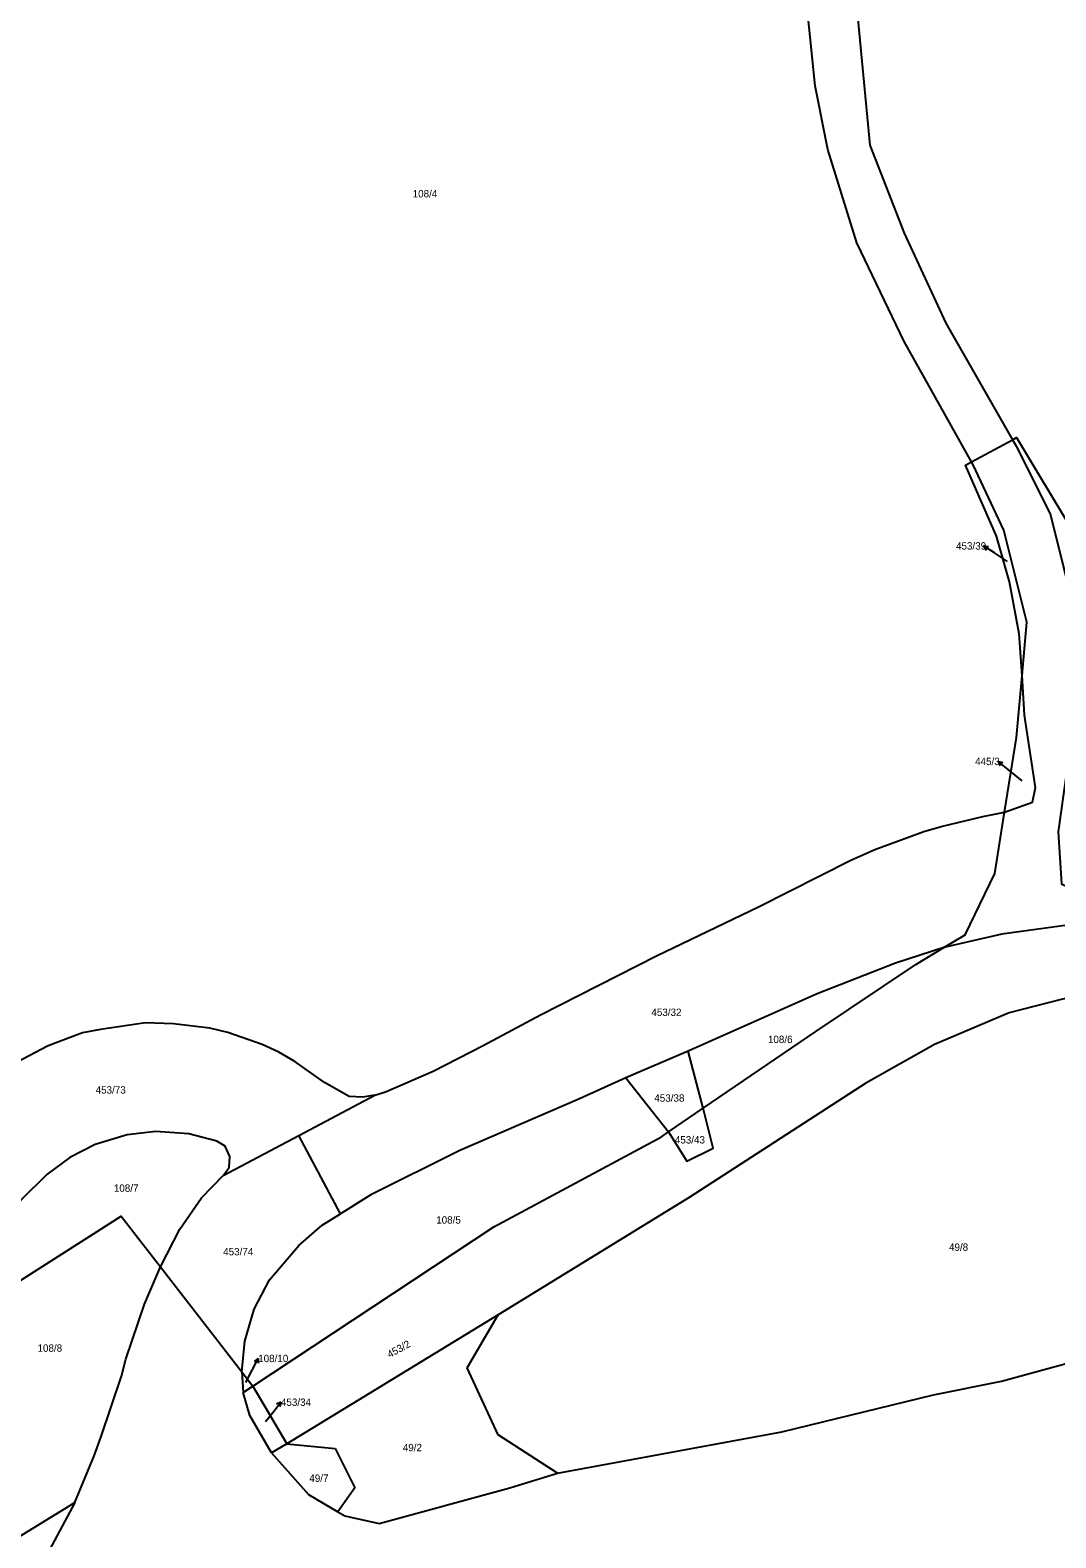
# Model space of a CAD drawing. Extents: x -882150 to -879379, y -1022570 to -1019819.
# Drawn here: x -880115.3 to -879878.6, y -1020796.9 to -1020448.8 of the extents above; entities that cross this region are included whole.
import ezdxf

# ---------------------------------------------------------------- set-up
doc = ezdxf.new("R2010")
doc.units = 0
for name, color, linetype in [('Hranice parcel', 7, 'Continuous'), ('Parcelní čísla', 7, 'Continuous'), ('Pop  PČ popisy', 7, 'Continuous')]:
    doc.layers.add(name, color=color, linetype=linetype)

msp = doc.modelspace()

# ---------------------------------------------------------------- linework, layer by layer
at = {"layer": 'Hranice parcel'}
for p, q in [((-879898.06, -1020548.48), (-879888.6, -1020543.4)), ((-879963.44, -1020684.54), (-879977.82, -1020690.75)), ((-879960.03, -1020697.74), (-879963.44, -1020684.54)), ((-879977.82, -1020690.75), (-879967.98, -1020703.17)), ((-880053.28, -1020704), (-880035.79, -1020694.72)), ((-879967.98, -1020703.17), (-879960.03, -1020697.74)), ((-880070.77, -1020713.27), (-880053.28, -1020704)), ((-880043.69, -1020722.08), (-880053.28, -1020704)), ((-880085.25, -1020734.33), (-880066.49, -1020758.57)), ((-880007.29, -1020745.44), (-880056.08, -1020775.19)), ((-880014.47, -1020757.68), (-880007.29, -1020745.44)), ((-880066.49, -1020758.57), (-880063.93, -1020761.87)), ((-880066.49, -1020758.57), (-880066.15, -1020763.39)), ((-880007.34, -1020773.15), (-880014.47, -1020757.68)), ((-880066.15, -1020763.39), (-880063.93, -1020761.87)), ((-880063.93, -1020761.87), (-880056.08, -1020775.19)), ((-880056.08, -1020775.19), (-880059.59, -1020777.26)), ((-880056.08, -1020775.19), (-880044.95, -1020776.27)), ((-879993.6, -1020781.97), (-880007.34, -1020773.15))]:
    msp.add_line(p, q, dxfattribs=at)
for points in [[(-879898.06, -1020548.48), (-879913.62, -1020520.69), (-879924.52, -1020497.9), (-879931.26, -1020476.35), (-879934.19, -1020461.7), (-879938.41, -1020420.22), (-879947.88, -1020362.58), (-879952, -1020338.2), (-879958.23, -1020317.82), (-879965.31, -1020303.46), (-879975.02, -1020294.36), (-880006.56, -1020250.49), (-880042.35, -1020206.21)], [(-880019.8, -1020217.31), (-880003.48, -1020236.2), (-879967.5, -1020277.69), (-879952.67, -1020298.78), (-879946.03, -1020310.63), (-879939.11, -1020336.56), (-879926.82, -1020417.09), (-879924.34, -1020446.28), (-879921.53, -1020475.37), (-879913.62, -1020495.71), (-879903.98, -1020516.47), (-879888.6, -1020543.4)], [(-879888.6, -1020543.4), (-879887.68, -1020542.9), (-879874.66, -1020564.64), (-879869.28, -1020574.02), (-879866.55, -1020579.31), (-879865.33, -1020582.41), (-879862.95, -1020589.58), (-879860.41, -1020600.26), (-879858.85, -1020610.83), (-879857.98, -1020621.89), (-879856.66, -1020625.28), (-879854.09, -1020626.63), (-879845.37, -1020627.31), (-879834.53, -1020628.82), (-879823.81, -1020631.02), (-879808.01, -1020635.54), (-879797.85, -1020639.13), (-879773.76, -1020649.14), (-879769.33, -1020652.27), (-879772.63, -1020658.91)], [(-879888.6, -1020543.4), (-879887.69, -1020544.98), (-879879.83, -1020560.74), (-879873.67, -1020585.51), (-879874.91, -1020611.47), (-879878.08, -1020633.92), (-879877.33, -1020645.9), (-879869.99, -1020649.38), (-879830.84, -1020645.01), (-879800.86, -1020646.94), (-879787.95, -1020649.9), (-879776.47, -1020654.35), (-879772.63, -1020658.91)], [(-879886.42, -1020597.82), (-879887.06, -1020588.22), (-879889.32, -1020576.23), (-879892.34, -1020565.69), (-879899.5, -1020549.25), (-879898.06, -1020548.48)], [(-879886.42, -1020597.82), (-879885.35, -1020585.52), (-879890.65, -1020564.27), (-879897.68, -1020549.16), (-879898.06, -1020548.48)], [(-879890.44, -1020629.39), (-879887.67, -1020612.12), (-879886.42, -1020597.82)], [(-879890.44, -1020629.39), (-879884.02, -1020627.07), (-879883.29, -1020623.66), (-879885.82, -1020606.97), (-879886.42, -1020597.82)], [(-880035.79, -1020694.72), (-880033.31, -1020693.92), (-880022.31, -1020689.21), (-880010.79, -1020683.27), (-879997.55, -1020676.15), (-879970.76, -1020662.58), (-879947.22, -1020651.2), (-879925.96, -1020640.49), (-879920.43, -1020638), (-879909.12, -1020633.87), (-879905.06, -1020632.66), (-879895.46, -1020630.4), (-879890.44, -1020629.39)], [(-879904.5, -1020660.66), (-879899.55, -1020657.68), (-879892.72, -1020643.57), (-879890.44, -1020629.39)], [(-879817.33, -1020662), (-879838.04, -1020655.79), (-879870.99, -1020656.01), (-879875.36, -1020655.41), (-879891.09, -1020657.52), (-879904.5, -1020660.66)], [(-879904.5, -1020660.66), (-879915.62, -1020664.22), (-879933.72, -1020671.33), (-879963.44, -1020684.54)], [(-879960.03, -1020697.74), (-879934.03, -1020679.99), (-879910.9, -1020664.51), (-879904.5, -1020660.66)], [(-879805.81, -1020667.04), (-879831.43, -1020664.89), (-879855.31, -1020667.58), (-879877.4, -1020672.6), (-879889.36, -1020675.71), (-879906.65, -1020682.99), (-879922.47, -1020691.94), (-879963.22, -1020718.34), (-880007.29, -1020745.44)], [(-880035.79, -1020694.72), (-880038.55, -1020695.14), (-880041.67, -1020695.04), (-880047.39, -1020691.8), (-880054.24, -1020686.91), (-880057.91, -1020684.79), (-880061.74, -1020683), (-880069.71, -1020680.22), (-880073.85, -1020679.23), (-880082.24, -1020678.22), (-880088.65, -1020678.05), (-880099.06, -1020679.52), (-880103.2, -1020680.35), (-880111.13, -1020683.34), (-880118.61, -1020687.27)], [(-879977.82, -1020690.75), (-879988.58, -1020695.59), (-880016.12, -1020707.47), (-880036.67, -1020717.69), (-880043.69, -1020722.08)], [(-879967.98, -1020703.17), (-879963.77, -1020709.98), (-879957.66, -1020706.93), (-879960.03, -1020697.74)], [(-880070.77, -1020713.27), (-880069.41, -1020711.42), (-880069.23, -1020708.91), (-880070.33, -1020706.52), (-880072.26, -1020705.33), (-880078.68, -1020703.61), (-880086.33, -1020703.09), (-880092.94, -1020703.88), (-880100.29, -1020706.14), (-880106.13, -1020709.1), (-880111.46, -1020713.02), (-880117.31, -1020718.77), (-880123.56, -1020726.71), (-880139.93, -1020751.73)], [(-880063.93, -1020761.87), (-880008.32, -1020725.12), (-879969.65, -1020704.31), (-879967.98, -1020703.17)], [(-880085.25, -1020734.33), (-880080.73, -1020725.62), (-880075.78, -1020718.44), (-880070.77, -1020713.27)], [(-880139.93, -1020751.73), (-880094.28, -1020722.66), (-880085.25, -1020734.33)], [(-880066.49, -1020758.57), (-880065.79, -1020751.53), (-880063.64, -1020744.15), (-880060.06, -1020737.33), (-880053.32, -1020729.4), (-880047.93, -1020724.74), (-880043.69, -1020722.08)], [(-880104.98, -1020788.72), (-880100.56, -1020777.96), (-880098.9, -1020773.51), (-880094.22, -1020759.61), (-880093.25, -1020755.63), (-880088.89, -1020742.94), (-880085.25, -1020734.33)], [(-879891.14, -1020760.75), (-879832.12, -1020744.62), (-879826.76, -1020743.13), (-879825.01, -1020742.84)], [(-879993.6, -1020781.97), (-879941.89, -1020772.44), (-879906.84, -1020763.89), (-879891.14, -1020760.75)], [(-880059.59, -1020777.26), (-880064.61, -1020768.64), (-880066.15, -1020763.39)], [(-880044.95, -1020776.27), (-880040.36, -1020785.35), (-880044.32, -1020790.88)], [(-880059.59, -1020777.26), (-880051.08, -1020786.88), (-880044.32, -1020790.88)], [(-880034.78, -1020793.59), (-880004.64, -1020785.35), (-879993.6, -1020781.97)], [(-880242.62, -1020869.86), (-880226.61, -1020861.09), (-880170.66, -1020829.12), (-880104.98, -1020788.72)], [(-880104.98, -1020788.72), (-880110.84, -1020799.71), (-880116.96, -1020809.22), (-880122.17, -1020815.79)], [(-880044.32, -1020790.88), (-880042.72, -1020791.83), (-880034.78, -1020793.59)]]:
    msp.add_lwpolyline(points, dxfattribs=at)
at = {"layer": 'Pop  PČ popisy'}
for p, q in [((-879892.79, -1020569.54), (-879895.307, -1020567.906)), ((-879895.307, -1020567.906), (-879894.194, -1020568.031)), ((-879895.307, -1020567.906), (-879894.74, -1020568.871)), ((-879889.77, -1020571.5), (-879892.79, -1020569.54)), ((-879889.62, -1020619.54), (-879891.952, -1020617.651)), ((-879891.952, -1020617.651), (-879890.859, -1020617.893)), ((-879891.952, -1020617.651), (-879891.489, -1020618.671)), ((-879886.43, -1020622.11), (-879889.62, -1020619.54)), ((-880064.05, -1020758.18), (-880062.688, -1020755.506)), ((-880062.688, -1020755.506), (-880063.588, -1020756.171)), ((-880062.688, -1020755.506), (-880062.696, -1020756.626)), ((-880065.52, -1020761.07), (-880064.05, -1020758.18)), ((-880059.32, -1020767.94), (-880057.431, -1020765.608)), ((-880057.431, -1020765.608), (-880058.451, -1020766.071)), ((-880057.431, -1020765.608), (-880057.673, -1020766.701)), ((-880061.01, -1020770.05), (-880059.32, -1020767.94))]:
    msp.add_line(p, q, dxfattribs=at)

# ---------------------------------------------------------------- texts
at = {"layer": 'Parcelní čísla'}
for s, p in [('108/4', (-880027.04, -1020487.45)), ('453/39', (-879901.665, -1020568.75)), ('445/3', (-879897.256, -1020618.51)), ('453/32', (-879971.958, -1020676.43)), ('108/6', (-879945.07, -1020682.69)), ('453/73', (-880100.191, -1020694.35)), ('453/38', (-879971.28, -1020696.22)), ('453/43', (-879966.54, -1020705.87)), ('108/7', (-880095.99, -1020717.03)), ('108/5', (-880021.61, -1020724.37)), ('453/74', (-880070.764, -1020731.7)), ('49/8', (-879903.28, -1020730.65)), ('108/8', (-880113.61, -1020753.96)), ('108/10', (-880062.69, -1020756.35)), ('453/34', (-880057.44, -1020766.45)), ('49/2', (-880029.32, -1020776.92)), ('49/7', (-880050.89, -1020783.99))]:
    msp.add_text(s, height=1.7, dxfattribs=at).set_placement(p)
msp.add_text('453/2', height=1.7, rotation=29, dxfattribs=at).set_placement((-880032.347, -1020755.433))

doc.saveas('drawing.dxf')
